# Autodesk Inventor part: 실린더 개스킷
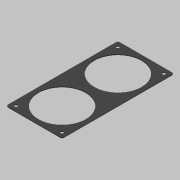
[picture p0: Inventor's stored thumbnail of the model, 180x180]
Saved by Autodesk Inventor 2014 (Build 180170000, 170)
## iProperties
Created: 2019-08
Part Number: 실린더 개스킷
Material: 고무
Document SubType Name: Modeling
Designer: mduedu
Density: 0.93 g/cm^3
Appearance: 고무 - 검은색 - 버전 1.1
Mass: 5.78528 g
Surface Area: 134.615 cm^2
Volume: 6.22073 cm^3
Author: mduedu
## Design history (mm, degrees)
sketch "스케치1"
  geometry: L1 (42.5, -42.5)-(-42.5, -42.5); L2 (-42.5, -42.5)-(-42.5, 127.5); L3 (-42.5, 127.5)-(42.5, 127.5); L4 (42.5, 127.5)-(42.5, -42.5); 2 further points
  constraints: 8 end point, 2 parallel, 1 horizontal, 1 midpoint, 1 perpendicular, 1 vertical alignment
  dimensions: "d1" = 85 distance of L1.start L1.end; "d3" = 170 distance of L3.end L1.start; "d4" = 42.5 distance from line of L1 point (0, 0)
extrude "돌출1" new body sketch "스케치1" distance "d5" = 1; taper "d6" = 0 deg
sketch "스케치2"
  geometry: C1 r 36 at (0, 0); C2 r 36 at (0, 85); 1 further point
  constraints: 2 centre point, 1 coincident, 1 vertical alignment
  dimensions: "d7" = 72 diameter of C1; "d8" = 72 diameter of C2; "d9" = 85 distance of C2.centre point (0, 0)
extrude "돌출2" cut sketch "스케치2" stored distance "d10" = 1; taper "d11" = 0 deg
sketch "스케치3"
  geometry: L1 (-35, -35)-(35, -35); L2 (35, -35)-(35, 35); L3 (35, 35)-(-35, 35); L4 (-35, 35)-(-35, -35); L5 (-35, -35)-(35, 35); L6 (35, -35)-(-35, 35); L7 (-35, 50)-(35, 50); L8 (35, 50)-(35, 120); L9 (35, 120)-(-35, 120); L10 (-35, 120)-(-35, 50); L11 (-35, 50)-(35, 120); L12 (35, 50)-(-35, 120); C1 r 36 at (0, 85) reference; 5 further points
  constraints: 24 end point, 4 coincident, 4 midpoint, 4 parallel, 2 horizontal, 2 perpendicular
  dimensions: "d12" = 70 distance of L3.end L2.end; "d13" = 70 distance of L2.end L1.end; "d14" = 70 distance of L9.end L8.end; "d15" = 70 distance of L8.end L7.end
hole "구멍1" sketch "스케치3" at (35, -35), (-35, -35), (-35, 120), (35, 120) diameter "d16" = 5; stored, may be unused: countersink angle "d20" = 90 deg, drill point angle "d22" = 118 deg; dims "d17" = 6, "d18" = 4, "d19" = 2, "d21" = 8
fillet "모깎기1" dims "d23" = 3
node "솔리드2"
node "솔리드1"
